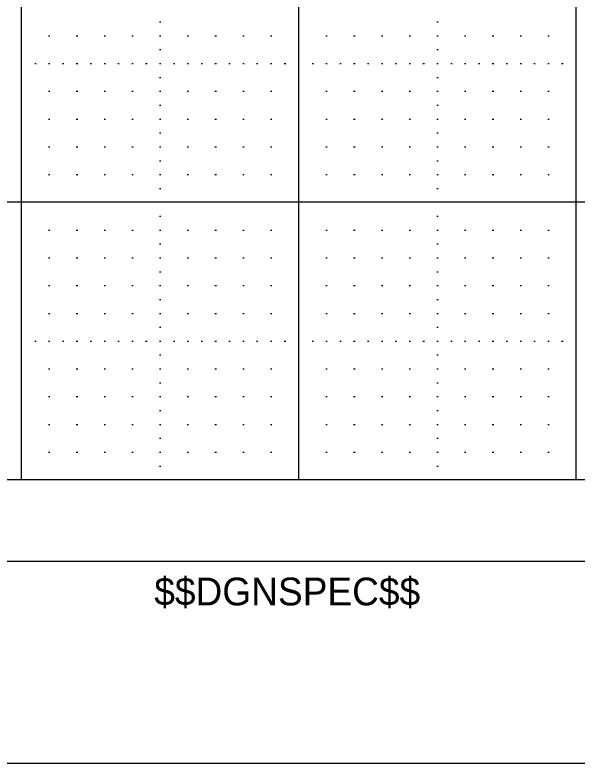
# Model space of a CAD drawing. Extents: x -1.6 to 32.7, y -1.7 to 21.9.
# Drawn here: x 21.721 to 23.748, y -0.727 to 1.968 of the extents above; entities that cross this region are included whole.
import ezdxf

# ---------------------------------------------------------------- set-up
doc = ezdxf.new("R2010")
doc.units = 0
for name, color, linetype in [('Level 1', 7, 'Continuous'), ('Level 4', 7, 'Continuous'), ('Level 48', 7, 'Continuous'), ('Level 5', 7, 'Continuous'), ('Level 63', 7, 'Continuous'), ('R_Border_Dark', 7, 'Continuous')]:
    doc.layers.add(name, color=color, linetype=linetype)

msp = doc.modelspace()

# ---------------------------------------------------------------- linework, layer by layer
at = {"layer": 'Level 1'}
msp.add_line((31.617, -0.001), (-0.001, -0.001), dxfattribs=at)
msp.add_lwpolyline([(0.745, 10.272), (30.745, 10.272), (30.745, 0.293), (0.745, 0.293)], close=True, dxfattribs=at)
at = {"layer": 'Level 4'}
msp.add_line((31.617, 0.293), (-0.001, 0.293), dxfattribs=at)
at = {"layer": 'Level 5'}
for p, q in [((22.2425, 1.943), (22.2475, 1.943)), ((23.2425, 1.943), (23.2475, 1.943)), ((21.8425, 1.893), (21.8475, 1.893)), ((21.9425, 1.893), (21.9475, 1.893)), ((22.0425, 1.893), (22.0475, 1.893)), ((22.1425, 1.893), (22.1475, 1.893)), ((22.2425, 1.893), (22.2475, 1.893)), ((22.3425, 1.893), (22.3475, 1.893)), ((22.4425, 1.893), (22.4475, 1.893)), ((22.5425, 1.893), (22.5475, 1.893)), ((22.6425, 1.893), (22.6475, 1.893)), ((22.8425, 1.893), (22.8475, 1.893)), ((22.9425, 1.893), (22.9475, 1.893)), ((23.0425, 1.893), (23.0475, 1.893)), ((23.1425, 1.893), (23.1475, 1.893)), ((23.2425, 1.893), (23.2475, 1.893)), ((23.3425, 1.893), (23.3475, 1.893)), ((23.4425, 1.893), (23.4475, 1.893)), ((23.5425, 1.893), (23.5475, 1.893)), ((23.6425, 1.893), (23.6475, 1.893)), ((22.2425, 1.843), (22.2475, 1.843)), ((23.2425, 1.843), (23.2475, 1.843)), ((21.7925, 1.793), (21.7975, 1.793)), ((21.8425, 1.793), (21.8475, 1.793)), ((21.8925, 1.793), (21.8975, 1.793)), ((21.9425, 1.793), (21.9475, 1.793)), ((21.9925, 1.793), (21.9975, 1.793)), ((22.0425, 1.793), (22.0475, 1.793)), ((22.0925, 1.793), (22.0975, 1.793)), ((22.1425, 1.793), (22.1475, 1.793)), ((22.1925, 1.793), (22.1975, 1.793)), ((22.2425, 1.793), (22.2475, 1.793)), ((22.2925, 1.793), (22.2975, 1.793)), ((22.3425, 1.793), (22.3475, 1.793)), ((22.3925, 1.793), (22.3975, 1.793)), ((22.4425, 1.793), (22.4475, 1.793)), ((22.4925, 1.793), (22.4975, 1.793)), ((22.5425, 1.793), (22.5475, 1.793)), ((22.5925, 1.793), (22.5975, 1.793)), ((22.6425, 1.793), (22.6475, 1.793)), ((22.6925, 1.793), (22.6975, 1.793)), ((22.7925, 1.793), (22.7975, 1.793)), ((22.8425, 1.793), (22.8475, 1.793)), ((22.8925, 1.793), (22.8975, 1.793)), ((22.9425, 1.793), (22.9475, 1.793)), ((22.9925, 1.793), (22.9975, 1.793)), ((23.0425, 1.793), (23.0475, 1.793)), ((23.0925, 1.793), (23.0975, 1.793)), ((23.1425, 1.793), (23.1475, 1.793)), ((23.1925, 1.793), (23.1975, 1.793)), ((23.2425, 1.793), (23.2475, 1.793)), ((23.2925, 1.793), (23.2975, 1.793)), ((23.3425, 1.793), (23.3475, 1.793)), ((23.3925, 1.793), (23.3975, 1.793)), ((23.4425, 1.793), (23.4475, 1.793)), ((23.4925, 1.793), (23.4975, 1.793)), ((23.5425, 1.793), (23.5475, 1.793)), ((23.5925, 1.793), (23.5975, 1.793)), ((23.6425, 1.793), (23.6475, 1.793)), ((23.6925, 1.793), (23.6975, 1.793)), ((22.2425, 1.743), (22.2475, 1.743)), ((23.2425, 1.743), (23.2475, 1.743)), ((21.8425, 1.693), (21.8475, 1.693)), ((21.9425, 1.693), (21.9475, 1.693)), ((22.0425, 1.693), (22.0475, 1.693)), ((22.1425, 1.693), (22.1475, 1.693)), ((22.2425, 1.693), (22.2475, 1.693)), ((22.3425, 1.693), (22.3475, 1.693)), ((22.4425, 1.693), (22.4475, 1.693)), ((22.5425, 1.693), (22.5475, 1.693)), ((22.6425, 1.693), (22.6475, 1.693)), ((22.8425, 1.693), (22.8475, 1.693)), ((22.9425, 1.693), (22.9475, 1.693)), ((23.0425, 1.693), (23.0475, 1.693)), ((23.1425, 1.693), (23.1475, 1.693)), ((23.2425, 1.693), (23.2475, 1.693)), ((23.3425, 1.693), (23.3475, 1.693)), ((23.4425, 1.693), (23.4475, 1.693)), ((23.5425, 1.693), (23.5475, 1.693)), ((23.6425, 1.693), (23.6475, 1.693)), ((22.2425, 1.643), (22.2475, 1.643)), ((23.2425, 1.643), (23.2475, 1.643)), ((21.8425, 1.593), (21.8475, 1.593)), ((21.9425, 1.593), (21.9475, 1.593)), ((22.0425, 1.593), (22.0475, 1.593)), ((22.1425, 1.593), (22.1475, 1.593)), ((22.2425, 1.593), (22.2475, 1.593)), ((22.3425, 1.593), (22.3475, 1.593)), ((22.4425, 1.593), (22.4475, 1.593)), ((22.5425, 1.593), (22.5475, 1.593)), ((22.6425, 1.593), (22.6475, 1.593)), ((22.8425, 1.593), (22.8475, 1.593)), ((22.9425, 1.593), (22.9475, 1.593)), ((23.0425, 1.593), (23.0475, 1.593)), ((23.1425, 1.593), (23.1475, 1.593)), ((23.2425, 1.593), (23.2475, 1.593)), ((23.3425, 1.593), (23.3475, 1.593)), ((23.4425, 1.593), (23.4475, 1.593)), ((23.5425, 1.593), (23.5475, 1.593)), ((23.6425, 1.593), (23.6475, 1.593)), ((22.2425, 1.543), (22.2475, 1.543)), ((23.2425, 1.543), (23.2475, 1.543)), ((21.8425, 1.493), (21.8475, 1.493)), ((21.9425, 1.493), (21.9475, 1.493)), ((22.0425, 1.493), (22.0475, 1.493)), ((22.1425, 1.493), (22.1475, 1.493)), ((22.2425, 1.493), (22.2475, 1.493)), ((22.3425, 1.493), (22.3475, 1.493)), ((22.4425, 1.493), (22.4475, 1.493)), ((22.5425, 1.493), (22.5475, 1.493)), ((22.6425, 1.493), (22.6475, 1.493)), ((22.8425, 1.493), (22.8475, 1.493)), ((22.9425, 1.493), (22.9475, 1.493)), ((23.0425, 1.493), (23.0475, 1.493)), ((23.1425, 1.493), (23.1475, 1.493)), ((23.2425, 1.493), (23.2475, 1.493)), ((23.3425, 1.493), (23.3475, 1.493)), ((23.4425, 1.493), (23.4475, 1.493)), ((23.5425, 1.493), (23.5475, 1.493)), ((23.6425, 1.493), (23.6475, 1.493)), ((22.2425, 1.443), (22.2475, 1.443)), ((23.2425, 1.443), (23.2475, 1.443)), ((21.8425, 1.393), (21.8475, 1.393)), ((21.9425, 1.393), (21.9475, 1.393)), ((22.0425, 1.393), (22.0475, 1.393)), ((22.1425, 1.393), (22.1475, 1.393)), ((22.2425, 1.393), (22.2475, 1.393)), ((22.3425, 1.393), (22.3475, 1.393)), ((22.4425, 1.393), (22.4475, 1.393)), ((22.5425, 1.393), (22.5475, 1.393)), ((22.6425, 1.393), (22.6475, 1.393)), ((22.8425, 1.393), (22.8475, 1.393)), ((22.9425, 1.393), (22.9475, 1.393)), ((23.0425, 1.393), (23.0475, 1.393)), ((23.1425, 1.393), (23.1475, 1.393)), ((23.2425, 1.393), (23.2475, 1.393)), ((23.3425, 1.393), (23.3475, 1.393)), ((23.4425, 1.393), (23.4475, 1.393)), ((23.5425, 1.393), (23.5475, 1.393)), ((23.6425, 1.393), (23.6475, 1.393)), ((22.2425, 1.343), (22.2475, 1.343)), ((23.2425, 1.343), (23.2475, 1.343)), ((22.2425, 1.243), (22.2475, 1.243)), ((23.2425, 1.243), (23.2475, 1.243)), ((21.8425, 1.193), (21.8475, 1.193)), ((21.9425, 1.193), (21.9475, 1.193)), ((22.0425, 1.193), (22.0475, 1.193)), ((22.1425, 1.193), (22.1475, 1.193)), ((22.2425, 1.193), (22.2475, 1.193)), ((22.3425, 1.193), (22.3475, 1.193)), ((22.4425, 1.193), (22.4475, 1.193)), ((22.5425, 1.193), (22.5475, 1.193)), ((22.6425, 1.193), (22.6475, 1.193)), ((22.8425, 1.193), (22.8475, 1.193)), ((22.9425, 1.193), (22.9475, 1.193)), ((23.0425, 1.193), (23.0475, 1.193)), ((23.1425, 1.193), (23.1475, 1.193)), ((23.2425, 1.193), (23.2475, 1.193)), ((23.3425, 1.193), (23.3475, 1.193)), ((23.4425, 1.193), (23.4475, 1.193)), ((23.5425, 1.193), (23.5475, 1.193)), ((23.6425, 1.193), (23.6475, 1.193)), ((22.2425, 1.143), (22.2475, 1.143)), ((23.2425, 1.143), (23.2475, 1.143)), ((21.8425, 1.093), (21.8475, 1.093)), ((21.9425, 1.093), (21.9475, 1.093)), ((22.0425, 1.093), (22.0475, 1.093)), ((22.1425, 1.093), (22.1475, 1.093)), ((22.2425, 1.093), (22.2475, 1.093)), ((22.3425, 1.093), (22.3475, 1.093)), ((22.4425, 1.093), (22.4475, 1.093)), ((22.5425, 1.093), (22.5475, 1.093)), ((22.6425, 1.093), (22.6475, 1.093)), ((22.8425, 1.093), (22.8475, 1.093)), ((22.9425, 1.093), (22.9475, 1.093)), ((23.0425, 1.093), (23.0475, 1.093)), ((23.1425, 1.093), (23.1475, 1.093)), ((23.2425, 1.093), (23.2475, 1.093)), ((23.3425, 1.093), (23.3475, 1.093)), ((23.4425, 1.093), (23.4475, 1.093)), ((23.5425, 1.093), (23.5475, 1.093)), ((23.6425, 1.093), (23.6475, 1.093)), ((22.2425, 1.043), (22.2475, 1.043)), ((23.2425, 1.043), (23.2475, 1.043)), ((21.8425, 0.993), (21.8475, 0.993)), ((21.9425, 0.993), (21.9475, 0.993)), ((22.0425, 0.993), (22.0475, 0.993)), ((22.1425, 0.993), (22.1475, 0.993)), ((22.2425, 0.993), (22.2475, 0.993)), ((22.3425, 0.993), (22.3475, 0.993)), ((22.4425, 0.993), (22.4475, 0.993)), ((22.5425, 0.993), (22.5475, 0.993)), ((22.6425, 0.993), (22.6475, 0.993)), ((22.8425, 0.993), (22.8475, 0.993)), ((22.9425, 0.993), (22.9475, 0.993)), ((23.0425, 0.993), (23.0475, 0.993)), ((23.1425, 0.993), (23.1475, 0.993)), ((23.2425, 0.993), (23.2475, 0.993)), ((23.3425, 0.993), (23.3475, 0.993)), ((23.4425, 0.993), (23.4475, 0.993)), ((23.5425, 0.993), (23.5475, 0.993)), ((23.6425, 0.993), (23.6475, 0.993)), ((22.2425, 0.943), (22.2475, 0.943)), ((23.2425, 0.943), (23.2475, 0.943)), ((21.8425, 0.893), (21.8475, 0.893)), ((21.9425, 0.893), (21.9475, 0.893)), ((22.0425, 0.893), (22.0475, 0.893)), ((22.1425, 0.893), (22.1475, 0.893)), ((22.2425, 0.893), (22.2475, 0.893)), ((22.3425, 0.893), (22.3475, 0.893)), ((22.4425, 0.893), (22.4475, 0.893)), ((22.5425, 0.893), (22.5475, 0.893)), ((22.6425, 0.893), (22.6475, 0.893)), ((22.8425, 0.893), (22.8475, 0.893)), ((22.9425, 0.893), (22.9475, 0.893)), ((23.0425, 0.893), (23.0475, 0.893)), ((23.1425, 0.893), (23.1475, 0.893)), ((23.2425, 0.893), (23.2475, 0.893)), ((23.3425, 0.893), (23.3475, 0.893)), ((23.4425, 0.893), (23.4475, 0.893)), ((23.5425, 0.893), (23.5475, 0.893)), ((23.6425, 0.893), (23.6475, 0.893)), ((22.2425, 0.843), (22.2475, 0.843)), ((23.2425, 0.843), (23.2475, 0.843)), ((21.7925, 0.793), (21.7975, 0.793)), ((21.8425, 0.793), (21.8475, 0.793)), ((21.8925, 0.793), (21.8975, 0.793)), ((21.9425, 0.793), (21.9475, 0.793)), ((21.9925, 0.793), (21.9975, 0.793)), ((22.0425, 0.793), (22.0475, 0.793)), ((22.0925, 0.793), (22.0975, 0.793)), ((22.1425, 0.793), (22.1475, 0.793)), ((22.1925, 0.793), (22.1975, 0.793)), ((22.2425, 0.793), (22.2475, 0.793)), ((22.2925, 0.793), (22.2975, 0.793)), ((22.3425, 0.793), (22.3475, 0.793)), ((22.3925, 0.793), (22.3975, 0.793)), ((22.4425, 0.793), (22.4475, 0.793)), ((22.4925, 0.793), (22.4975, 0.793)), ((22.5425, 0.793), (22.5475, 0.793)), ((22.5925, 0.793), (22.5975, 0.793)), ((22.6425, 0.793), (22.6475, 0.793)), ((22.6925, 0.793), (22.6975, 0.793)), ((22.7925, 0.793), (22.7975, 0.793)), ((22.8425, 0.793), (22.8475, 0.793)), ((22.8925, 0.793), (22.8975, 0.793)), ((22.9425, 0.793), (22.9475, 0.793)), ((22.9925, 0.793), (22.9975, 0.793)), ((23.0425, 0.793), (23.0475, 0.793)), ((23.0925, 0.793), (23.0975, 0.793)), ((23.1425, 0.793), (23.1475, 0.793)), ((23.1925, 0.793), (23.1975, 0.793)), ((23.2425, 0.793), (23.2475, 0.793)), ((23.2925, 0.793), (23.2975, 0.793)), ((23.3425, 0.793), (23.3475, 0.793)), ((23.3925, 0.793), (23.3975, 0.793)), ((23.4425, 0.793), (23.4475, 0.793)), ((23.4925, 0.793), (23.4975, 0.793)), ((23.5425, 0.793), (23.5475, 0.793)), ((23.5925, 0.793), (23.5975, 0.793)), ((23.6425, 0.793), (23.6475, 0.793)), ((23.6925, 0.793), (23.6975, 0.793)), ((22.2425, 0.743), (22.2475, 0.743)), ((23.2425, 0.743), (23.2475, 0.743)), ((21.8425, 0.693), (21.8475, 0.693)), ((21.9425, 0.693), (21.9475, 0.693)), ((22.0425, 0.693), (22.0475, 0.693)), ((22.1425, 0.693), (22.1475, 0.693)), ((22.2425, 0.693), (22.2475, 0.693)), ((22.3425, 0.693), (22.3475, 0.693)), ((22.4425, 0.693), (22.4475, 0.693)), ((22.5425, 0.693), (22.5475, 0.693)), ((22.6425, 0.693), (22.6475, 0.693)), ((22.8425, 0.693), (22.8475, 0.693)), ((22.9425, 0.693), (22.9475, 0.693)), ((23.0425, 0.693), (23.0475, 0.693)), ((23.1425, 0.693), (23.1475, 0.693)), ((23.2425, 0.693), (23.2475, 0.693)), ((23.3425, 0.693), (23.3475, 0.693)), ((23.4425, 0.693), (23.4475, 0.693)), ((23.5425, 0.693), (23.5475, 0.693)), ((23.6425, 0.693), (23.6475, 0.693)), ((22.2425, 0.643), (22.2475, 0.643)), ((23.2425, 0.643), (23.2475, 0.643)), ((21.8425, 0.593), (21.8475, 0.593)), ((21.9425, 0.593), (21.9475, 0.593)), ((22.0425, 0.593), (22.0475, 0.593)), ((22.1425, 0.593), (22.1475, 0.593)), ((22.2425, 0.593), (22.2475, 0.593)), ((22.3425, 0.593), (22.3475, 0.593)), ((22.4425, 0.593), (22.4475, 0.593)), ((22.5425, 0.593), (22.5475, 0.593)), ((22.6425, 0.593), (22.6475, 0.593)), ((22.8425, 0.593), (22.8475, 0.593)), ((22.9425, 0.593), (22.9475, 0.593)), ((23.0425, 0.593), (23.0475, 0.593)), ((23.1425, 0.593), (23.1475, 0.593)), ((23.2425, 0.593), (23.2475, 0.593)), ((23.3425, 0.593), (23.3475, 0.593)), ((23.4425, 0.593), (23.4475, 0.593)), ((23.5425, 0.593), (23.5475, 0.593)), ((23.6425, 0.593), (23.6475, 0.593)), ((22.2425, 0.543), (22.2475, 0.543)), ((23.2425, 0.543), (23.2475, 0.543)), ((21.8425, 0.493), (21.8475, 0.493)), ((21.9425, 0.493), (21.9475, 0.493)), ((22.0425, 0.493), (22.0475, 0.493)), ((22.1425, 0.493), (22.1475, 0.493)), ((22.2425, 0.493), (22.2475, 0.493)), ((22.3425, 0.493), (22.3475, 0.493)), ((22.4425, 0.493), (22.4475, 0.493)), ((22.5425, 0.493), (22.5475, 0.493)), ((22.6425, 0.493), (22.6475, 0.493)), ((22.8425, 0.493), (22.8475, 0.493)), ((22.9425, 0.493), (22.9475, 0.493)), ((23.0425, 0.493), (23.0475, 0.493)), ((23.1425, 0.493), (23.1475, 0.493)), ((23.2425, 0.493), (23.2475, 0.493)), ((23.3425, 0.493), (23.3475, 0.493)), ((23.4425, 0.493), (23.4475, 0.493)), ((23.5425, 0.493), (23.5475, 0.493)), ((23.6425, 0.493), (23.6475, 0.493)), ((22.2425, 0.443), (22.2475, 0.443)), ((23.2425, 0.443), (23.2475, 0.443)), ((21.8425, 0.393), (21.8475, 0.393)), ((21.9425, 0.393), (21.9475, 0.393)), ((22.0425, 0.393), (22.0475, 0.393)), ((22.1425, 0.393), (22.1475, 0.393)), ((22.2425, 0.393), (22.2475, 0.393)), ((22.3425, 0.393), (22.3475, 0.393)), ((22.4425, 0.393), (22.4475, 0.393)), ((22.5425, 0.393), (22.5475, 0.393)), ((22.6425, 0.393), (22.6475, 0.393)), ((22.8425, 0.393), (22.8475, 0.393)), ((22.9425, 0.393), (22.9475, 0.393)), ((23.0425, 0.393), (23.0475, 0.393)), ((23.1425, 0.393), (23.1475, 0.393)), ((23.2425, 0.393), (23.2475, 0.393)), ((23.3425, 0.393), (23.3475, 0.393)), ((23.4425, 0.393), (23.4475, 0.393)), ((23.5425, 0.393), (23.5475, 0.393)), ((23.6425, 0.393), (23.6475, 0.393)), ((22.2425, 0.343), (22.2475, 0.343)), ((23.2425, 0.343), (23.2475, 0.343))]:
    msp.add_line(p, q, dxfattribs=at)
at = {"layer": 'Level 63'}
msp.add_lwpolyline([(-1.598, -0.727), (32.402, -0.727), (32.402, 21.273), (-1.598, 21.273)], close=True, dxfattribs=at)
msp.add_lwpolyline([(30.745, 8.293), (30.745, 0.293), (0.745, 0.293), (0.745, 8.293)], dxfattribs=at)
at = {"layer": 'R_Border_Dark'}
for p, q in [((21.745, 0.293), (21.745, 8.293)), ((22.745, 0.293), (22.745, 8.293)), ((23.745, 0.293), (23.745, 8.293)), ((31.617, 1.293), (-0.001, 1.293))]:
    msp.add_line(p, q, dxfattribs=at)
msp.add_lwpolyline([(30.745, 8.293), (30.745, 0.293), (0.745, 0.293), (0.745, 8.293)], dxfattribs=at)

# ---------------------------------------------------------------- texts
at = {"layer": 'Level 48'}
msp.add_text('$$DGNSPEC$$', height=0.100002, dxfattribs=at).set_placement((22.2236, -0.159))

doc.saveas('drawing.dxf')
